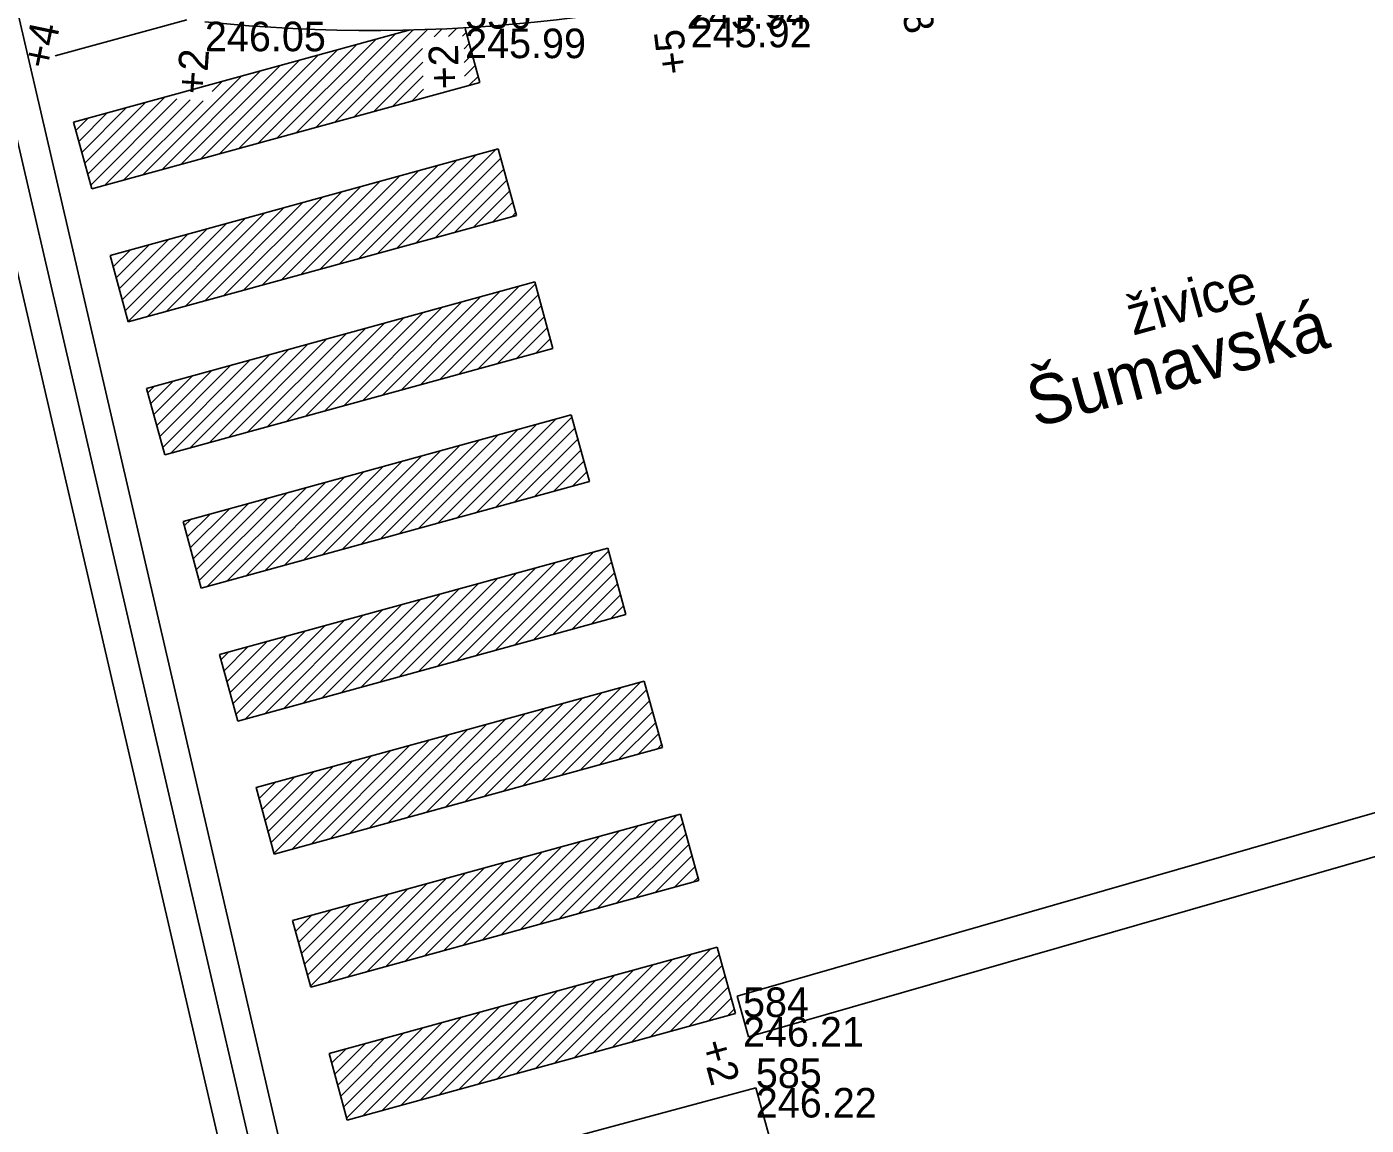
# Model space of a CAD drawing. Extents: x -599432 to -598680, y -1159407 to -1158632.
# Drawn here: x -599215.84 to -599202.25, y -1158959.67 to -1158948.52 of the extents above; entities that cross this region are included whole.
import ezdxf

# ---------------------------------------------------------------- set-up
doc = ezdxf.new("R2010")
doc.units = 0
for name, color, linetype in [('0004 VY - Body podrobné', 7, 'Continuous'), ('0005 VY - Body podrobné - čísla', 7, 'Continuous'), ('0006 VY - Body podrobné - výšky', 7, 'Continuous'), ('0024 ZA - Podezdívka', 7, 'Continuous'), ('0027 ZA - Silnice_cesta zpevněná', 7, 'Continuous'), ('0032 TE - Popis povrchu', 7, 'Continuous'), ('0048 TE - Názvy ulic _ náměstí', 7, 'Continuous'), ('0063 ZA - Doprava - vodorovné značení', 7, 'Continuous'), ('0073 TE - Výška obrubníků a zdí', 7, 'Continuous'), ('0652 PV - BKOM - kabely bez rozlišení', 7, 'Continuous'), ('0653 PV - BKOM - chranička', 7, 'Continuous')]:
    doc.layers.add(name, color=color, linetype=linetype)

msp = doc.modelspace()

# ---------------------------------------------------------------- linework, layer by layer
at = {"layer": '0004 VY - Body podrobné'}
for p, q in [((-599211.39, -1158948.54), (-599211.39, -1158948.54)), ((-599208.57, -1158958.57), (-599208.57, -1158958.57)), ((-599208.44, -1158959.29), (-599208.44, -1158959.29))]:
    msp.add_line(p, q, dxfattribs=at)
at = {"layer": '0024 ZA - Podezdívka'}
for p, q in [((-599208.629, -1158958.358), (-599184.09, -1158951.303)), ((-599208.514, -1158958.772), (-599183.95, -1158951.71)), ((-599208.514, -1158958.772), (-599208.629, -1158958.358))]:
    msp.add_line(p, q, dxfattribs=at)
at = {"layer": '0027 ZA - Silnice_cesta zpevněná'}
for p, q in [((-599214.067, -1158960.799), (-599208.44, -1158959.29)), ((-599208.44, -1158959.29), (-599207.51, -1158962.63))]:
    msp.add_line(p, q, dxfattribs=at)
msp.add_arc((-599212.336, -1158932.38), 16.179, 263.9914, 289.2961, dxfattribs=at)
at = {"layer": '0063 ZA - Doprava - vodorovné značení'}
for p, q in [((-599214.213, -1158948.45), (-599215.549, -1158948.816)), ((-599211.948, -1158948.554), (-599215.364, -1158949.491)), ((-599212.906, -1158949.543), (-599211.916, -1158948.553)), ((-599212.711, -1158949.49), (-599211.771, -1158948.549)), ((-599211.704, -1158948.623), (-599211.622, -1158948.542)), ((-599211.559, -1158948.62), (-599211.474, -1158948.535)), ((-599211.39, -1158948.54), (-599211.24, -1158949.086)), ((-599213.296, -1158949.65), (-599212.295, -1158948.65)), ((-599213.101, -1158949.596), (-599212.101, -1158948.596)), ((-599211.415, -1158948.617), (-599211.379, -1158948.581)), ((-599211.401, -1158948.745), (-599211.348, -1158948.692)), ((-599213.881, -1158949.81), (-599212.88, -1158948.81)), ((-599213.686, -1158949.757), (-599212.685, -1158948.757)), ((-599213.491, -1158949.703), (-599212.49, -1158948.703)), ((-599212.516, -1158949.436), (-599211.821, -1158948.741)), ((-599211.398, -1158948.883), (-599211.318, -1158948.803)), ((-599214.465, -1158949.971), (-599213.465, -1158948.97)), ((-599214.27, -1158949.917), (-599213.27, -1158948.917)), ((-599214.076, -1158949.864), (-599213.075, -1158948.863)), ((-599212.321, -1158949.383), (-599211.818, -1158948.879)), ((-599211.395, -1158949.022), (-599211.287, -1158948.914)), ((-599211.24, -1158949.086), (-599215.178, -1158950.167)), ((-599214.66, -1158950.024), (-599213.66, -1158949.024)), ((-599213.956, -1158949.179), (-599213.855, -1158949.077)), ((-599212.126, -1158949.329), (-599211.815, -1158949.018)), ((-599211.347, -1158949.115), (-599211.257, -1158949.025)), ((-599215.219, -1158950.018), (-599214.439, -1158949.238)), ((-599211.932, -1158949.276), (-599211.812, -1158949.156)), ((-599211.737, -1158949.222), (-599211.734, -1158949.219)), ((-599215.28, -1158949.796), (-599214.829, -1158949.345)), ((-599215.25, -1158949.907), (-599214.634, -1158949.291)), ((-599215.189, -1158950.129), (-599214.314, -1158949.253)), ((-599215.05, -1158950.131), (-599214.181, -1158949.262)), ((-599214.855, -1158950.078), (-599214.049, -1158949.272)), ((-599215.364, -1158949.491), (-599215.178, -1158950.167)), ((-599215.341, -1158949.574), (-599215.219, -1158949.452)), ((-599215.31, -1158949.685), (-599215.024, -1158949.398)), ((-599211.055, -1158949.761), (-599214.993, -1158950.842)), ((-599212.083, -1158950.769), (-599211.083, -1158949.769)), ((-599211.055, -1158949.761), (-599210.87, -1158950.436)), ((-599212.473, -1158950.876), (-599211.473, -1158949.876)), ((-599212.278, -1158950.822), (-599211.278, -1158949.822)), ((-599211.888, -1158950.715), (-599211.029, -1158949.856)), ((-599213.058, -1158951.036), (-599212.057, -1158950.036)), ((-599212.863, -1158950.983), (-599211.862, -1158949.982)), ((-599212.668, -1158950.929), (-599211.668, -1158949.929)), ((-599211.693, -1158950.662), (-599210.998, -1158949.967)), ((-599213.643, -1158951.197), (-599212.642, -1158950.196)), ((-599213.448, -1158951.143), (-599212.447, -1158950.143)), ((-599213.253, -1158951.09), (-599212.252, -1158950.089)), ((-599211.499, -1158950.608), (-599210.968, -1158950.078)), ((-599211.304, -1158950.555), (-599210.938, -1158950.189)), ((-599214.032, -1158951.304), (-599213.032, -1158950.303)), ((-599213.837, -1158951.25), (-599212.837, -1158950.25)), ((-599211.109, -1158950.502), (-599210.907, -1158950.3)), ((-599210.87, -1158950.436), (-599214.808, -1158951.517)), ((-599214.617, -1158951.464), (-599213.617, -1158950.464)), ((-599214.422, -1158951.411), (-599213.422, -1158950.41)), ((-599214.227, -1158951.357), (-599213.227, -1158950.357)), ((-599210.914, -1158950.448), (-599210.877, -1158950.411)), ((-599214.839, -1158951.403), (-599214.006, -1158950.571)), ((-599214.808, -1158951.514), (-599213.812, -1158950.517)), ((-599214.93, -1158951.07), (-599214.591, -1158950.731)), ((-599214.9, -1158951.181), (-599214.396, -1158950.678)), ((-599214.869, -1158951.292), (-599214.201, -1158950.624)), ((-599214.993, -1158950.842), (-599214.808, -1158951.517)), ((-599214.991, -1158950.848), (-599214.981, -1158950.838)), ((-599214.961, -1158950.959), (-599214.786, -1158950.785)), ((-599210.684, -1158951.111), (-599214.623, -1158952.192)), ((-599211.648, -1158952.101), (-599210.679, -1158951.132)), ((-599210.684, -1158951.111), (-599210.499, -1158951.786)), ((-599212.233, -1158952.262), (-599211.232, -1158951.261)), ((-599212.038, -1158952.208), (-599211.037, -1158951.208)), ((-599211.843, -1158952.155), (-599210.842, -1158951.154)), ((-599211.453, -1158952.048), (-599210.648, -1158951.243)), ((-599212.622, -1158952.369), (-599211.622, -1158951.368)), ((-599212.428, -1158952.315), (-599211.427, -1158951.315)), ((-599211.258, -1158951.994), (-599210.618, -1158951.354)), ((-599213.207, -1158952.529), (-599212.207, -1158951.529)), ((-599213.012, -1158952.476), (-599212.012, -1158951.475)), ((-599212.817, -1158952.422), (-599211.817, -1158951.422)), ((-599211.063, -1158951.941), (-599210.587, -1158951.465)), ((-599213.792, -1158952.69), (-599212.792, -1158951.689)), ((-599213.597, -1158952.636), (-599212.597, -1158951.636)), ((-599213.402, -1158952.583), (-599212.402, -1158951.582)), ((-599210.868, -1158951.887), (-599210.557, -1158951.576)), ((-599210.673, -1158951.834), (-599210.526, -1158951.687)), ((-599210.499, -1158951.786), (-599214.437, -1158952.867)), ((-599214.182, -1158952.797), (-599213.181, -1158951.796)), ((-599213.987, -1158952.743), (-599212.986, -1158951.743)), ((-599214.489, -1158952.679), (-599213.766, -1158951.957)), ((-599214.458, -1158952.79), (-599213.571, -1158951.903)), ((-599214.377, -1158952.85), (-599213.376, -1158951.85)), ((-599214.55, -1158952.457), (-599214.156, -1158952.064)), ((-599214.519, -1158952.568), (-599213.961, -1158952.01)), ((-599214.623, -1158952.192), (-599214.437, -1158952.867)), ((-599214.611, -1158952.235), (-599214.546, -1158952.171)), ((-599214.58, -1158952.346), (-599214.351, -1158952.117)), ((-599210.314, -1158952.461), (-599214.252, -1158953.542)), ((-599211.469, -1158953.504), (-599210.469, -1158952.503)), ((-599211.274, -1158953.45), (-599210.308, -1158952.484)), ((-599210.314, -1158952.461), (-599210.129, -1158953.136)), ((-599211.859, -1158953.611), (-599210.858, -1158952.61)), ((-599211.664, -1158953.557), (-599210.664, -1158952.557)), ((-599211.079, -1158953.397), (-599210.277, -1158952.595)), ((-599212.444, -1158953.771), (-599211.443, -1158952.771)), ((-599212.249, -1158953.718), (-599211.248, -1158952.717)), ((-599212.054, -1158953.664), (-599211.053, -1158952.664)), ((-599210.884, -1158953.343), (-599210.247, -1158952.706)), ((-599212.833, -1158953.878), (-599211.833, -1158952.878)), ((-599212.638, -1158953.825), (-599211.638, -1158952.824)), ((-599210.689, -1158953.29), (-599210.216, -1158952.817)), ((-599213.418, -1158954.039), (-599212.418, -1158953.038)), ((-599213.223, -1158953.985), (-599212.223, -1158952.985)), ((-599213.028, -1158953.932), (-599212.028, -1158952.931)), ((-599210.494, -1158953.236), (-599210.186, -1158952.928)), ((-599210.3, -1158953.183), (-599210.155, -1158953.039)), ((-599210.129, -1158953.136), (-599214.067, -1158954.217)), ((-599213.808, -1158954.146), (-599212.807, -1158953.145)), ((-599213.613, -1158954.092), (-599212.613, -1158953.092)), ((-599214.118, -1158954.031), (-599213.392, -1158953.306)), ((-599214.087, -1158954.142), (-599213.197, -1158953.252)), ((-599214.003, -1158954.199), (-599213.002, -1158953.199)), ((-599214.179, -1158953.809), (-599213.782, -1158953.413)), ((-599214.148, -1158953.92), (-599213.587, -1158953.359)), ((-599214.252, -1158953.542), (-599214.067, -1158954.217)), ((-599214.24, -1158953.587), (-599214.172, -1158953.52)), ((-599214.209, -1158953.698), (-599213.977, -1158953.466)), ((-599209.943, -1158953.811), (-599213.882, -1158954.892)), ((-599211.085, -1158954.85), (-599210.084, -1158953.85)), ((-599210.89, -1158954.797), (-599209.935, -1158953.842)), ((-599209.943, -1158953.811), (-599209.758, -1158954.486)), ((-599211.474, -1158954.957), (-599210.474, -1158953.957)), ((-599211.28, -1158954.904), (-599210.279, -1158953.903)), ((-599210.695, -1158954.743), (-599209.905, -1158953.953)), ((-599212.059, -1158955.118), (-599211.059, -1158954.117)), ((-599211.864, -1158955.064), (-599210.864, -1158954.064)), ((-599211.669, -1158955.011), (-599210.669, -1158954.01)), ((-599210.5, -1158954.69), (-599209.874, -1158954.064)), ((-599212.449, -1158955.225), (-599211.449, -1158954.224)), ((-599212.254, -1158955.171), (-599211.254, -1158954.171)), ((-599210.305, -1158954.636), (-599209.844, -1158954.175)), ((-599213.034, -1158955.385), (-599212.033, -1158954.385)), ((-599212.839, -1158955.332), (-599211.838, -1158954.331)), ((-599212.644, -1158955.278), (-599211.643, -1158954.278)), ((-599210.11, -1158954.583), (-599209.813, -1158954.286)), ((-599209.915, -1158954.529), (-599209.783, -1158954.397)), ((-599209.758, -1158954.486), (-599213.696, -1158955.567)), ((-599213.618, -1158955.545), (-599212.618, -1158954.545)), ((-599213.423, -1158955.492), (-599212.423, -1158954.492)), ((-599213.229, -1158955.439), (-599212.228, -1158954.438)), ((-599213.745, -1158955.389), (-599213.008, -1158954.652)), ((-599213.715, -1158955.5), (-599212.813, -1158954.599)), ((-599213.836, -1158955.056), (-599213.593, -1158954.813)), ((-599213.806, -1158955.167), (-599213.398, -1158954.759)), ((-599213.775, -1158955.278), (-599213.203, -1158954.706)), ((-599213.882, -1158954.892), (-599213.696, -1158955.567)), ((-599213.867, -1158954.945), (-599213.787, -1158954.866)), ((-599209.573, -1158955.161), (-599213.511, -1158956.242)), ((-599210.806, -1158956.226), (-599209.806, -1158955.225)), ((-599210.611, -1158956.172), (-599209.611, -1158955.172)), ((-599209.573, -1158955.161), (-599209.388, -1158955.836)), ((-599211.196, -1158956.332), (-599210.196, -1158955.332)), ((-599211.001, -1158956.279), (-599210.001, -1158955.279)), ((-599210.416, -1158956.119), (-599209.548, -1158955.251)), ((-599211.781, -1158956.493), (-599210.78, -1158955.493)), ((-599211.586, -1158956.439), (-599210.585, -1158955.439)), ((-599211.391, -1158956.386), (-599210.39, -1158955.386)), ((-599210.221, -1158956.065), (-599209.518, -1158955.362)), ((-599210.027, -1158956.012), (-599209.488, -1158955.473)), ((-599212.171, -1158956.6), (-599211.17, -1158955.6)), ((-599211.976, -1158956.546), (-599210.975, -1158955.546)), ((-599209.832, -1158955.958), (-599209.457, -1158955.584)), ((-599212.755, -1158956.76), (-599211.755, -1158955.76)), ((-599212.56, -1158956.707), (-599211.56, -1158955.706)), ((-599212.365, -1158956.653), (-599211.365, -1158955.653)), ((-599209.637, -1158955.905), (-599209.427, -1158955.695)), ((-599209.388, -1158955.836), (-599213.326, -1158956.917)), ((-599213.145, -1158956.867), (-599212.145, -1158955.867)), ((-599212.95, -1158956.814), (-599211.95, -1158955.813)), ((-599209.442, -1158955.851), (-599209.396, -1158955.806)), ((-599213.389, -1158956.687), (-599212.729, -1158956.027)), ((-599213.358, -1158956.798), (-599212.534, -1158955.974)), ((-599213.328, -1158956.909), (-599212.34, -1158955.92)), ((-599213.45, -1158956.465), (-599213.119, -1158956.134)), ((-599213.419, -1158956.576), (-599212.924, -1158956.081)), ((-599213.511, -1158956.243), (-599213.509, -1158956.241)), ((-599213.511, -1158956.242), (-599213.326, -1158956.917)), ((-599213.48, -1158956.354), (-599213.314, -1158956.188)), ((-599209.203, -1158956.511), (-599213.141, -1158957.592)), ((-599210.439, -1158957.576), (-599209.438, -1158956.576)), ((-599210.244, -1158957.523), (-599209.243, -1158956.523)), ((-599209.203, -1158956.511), (-599209.017, -1158957.186)), ((-599210.829, -1158957.683), (-599209.828, -1158956.683)), ((-599210.634, -1158957.63), (-599209.633, -1158956.63)), ((-599210.049, -1158957.469), (-599209.178, -1158956.599)), ((-599209.854, -1158957.416), (-599209.148, -1158956.71)), ((-599211.413, -1158957.844), (-599210.413, -1158956.843)), ((-599211.218, -1158957.79), (-599210.218, -1158956.79)), ((-599211.023, -1158957.737), (-599210.023, -1158956.736)), ((-599209.659, -1158957.362), (-599209.118, -1158956.821)), ((-599211.803, -1158957.951), (-599210.803, -1158956.95)), ((-599211.608, -1158957.897), (-599210.608, -1158956.897)), ((-599209.464, -1158957.309), (-599209.087, -1158956.932)), ((-599212.388, -1158958.111), (-599211.387, -1158957.111)), ((-599212.193, -1158958.058), (-599211.192, -1158957.057)), ((-599211.998, -1158958.004), (-599210.998, -1158957.004)), ((-599209.269, -1158957.256), (-599209.057, -1158957.043)), ((-599209.017, -1158957.186), (-599212.955, -1158958.267)), ((-599212.778, -1158958.218), (-599211.777, -1158957.218)), ((-599212.583, -1158958.165), (-599211.582, -1158957.164)), ((-599209.074, -1158957.202), (-599209.026, -1158957.154)), ((-599213.019, -1158958.035), (-599212.362, -1158957.378)), ((-599212.988, -1158958.146), (-599212.167, -1158957.325)), ((-599212.958, -1158958.257), (-599211.972, -1158957.271)), ((-599213.08, -1158957.813), (-599212.752, -1158957.485)), ((-599213.049, -1158957.924), (-599212.557, -1158957.432)), ((-599213.141, -1158957.592), (-599212.955, -1158958.267)), ((-599213.11, -1158957.702), (-599212.947, -1158957.539)), ((-599208.832, -1158957.861), (-599212.77, -1158958.942)), ((-599210.092, -1158958.933), (-599209.092, -1158957.933)), ((-599209.897, -1158958.88), (-599208.897, -1158957.879)), ((-599209.703, -1158958.826), (-599208.812, -1158957.935)), ((-599208.832, -1158957.861), (-599208.647, -1158958.536)), ((-599210.482, -1158959.04), (-599209.482, -1158958.04)), ((-599210.287, -1158958.987), (-599209.287, -1158957.986)), ((-599209.508, -1158958.773), (-599208.781, -1158958.046)), ((-599211.067, -1158959.201), (-599210.067, -1158958.2)), ((-599210.872, -1158959.147), (-599209.872, -1158958.147)), ((-599210.677, -1158959.094), (-599209.677, -1158958.093)), ((-599209.313, -1158958.719), (-599208.751, -1158958.157)), ((-599211.457, -1158959.308), (-599210.456, -1158958.307)), ((-599211.262, -1158959.254), (-599210.261, -1158958.254)), ((-599209.118, -1158958.666), (-599208.72, -1158958.268)), ((-599212.041, -1158959.468), (-599211.041, -1158958.468)), ((-599211.847, -1158959.415), (-599210.846, -1158958.414)), ((-599211.652, -1158959.361), (-599210.651, -1158958.361)), ((-599208.923, -1158958.612), (-599208.69, -1158958.379)), ((-599208.647, -1158958.536), (-599212.585, -1158959.617)), ((-599212.431, -1158959.575), (-599211.431, -1158958.575)), ((-599212.236, -1158959.522), (-599211.236, -1158958.521)), ((-599208.728, -1158958.559), (-599208.659, -1158958.49)), ((-599212.652, -1158959.372), (-599212.016, -1158958.735)), ((-599212.622, -1158959.483), (-599211.821, -1158958.682)), ((-599212.591, -1158959.594), (-599211.626, -1158958.628)), ((-599212.713, -1158959.15), (-599212.405, -1158958.842)), ((-599212.683, -1158959.261), (-599212.211, -1158958.789)), ((-599212.77, -1158958.942), (-599212.585, -1158959.617)), ((-599212.744, -1158959.039), (-599212.6, -1158958.896))]:
    msp.add_line(p, q, dxfattribs=at)
at = {"layer": '0652 PV - BKOM - kabely bez rozlišení'}
for points in [[(-599230.59, -1158974.37), (-599220.8, -1158971.75), (-599221.6, -1158968.7), (-599221.47, -1158967), (-599221.32, -1158965.59), (-599219.76, -1158963.71), (-599218.51, -1158962.9), (-599214.91, -1158961.78), (-599213.68, -1158961.96), (-599212.86, -1158962.94), (-599216.66, -1158946.55), (-599217.48, -1158945.68), (-599223.02, -1158942.57)], [(-599234.98, -1158975.02), (-599233.92, -1158975.36), (-599230.92, -1158974.46), (-599230.59, -1158974.37), (-599220.8, -1158971.75), (-599221.6, -1158968.7), (-599221.47, -1158967), (-599221.32, -1158965.59), (-599219.76, -1158963.71), (-599218.51, -1158962.9), (-599214.91, -1158961.78), (-599213.68, -1158961.96), (-599212.86, -1158962.94), (-599216.66, -1158946.55), (-599215.68, -1158946.71), (-599213.41, -1158947.28), (-599210.22, -1158947.13), (-599194.67, -1158942.89)]]:
    msp.add_lwpolyline(points, dxfattribs=at)
at = {"layer": '0653 PV - BKOM - chranička'}
for p, q in [((-599216.368, -1158946.482), (-599212.568, -1158962.872)), ((-599216.952, -1158946.618), (-599213.152, -1158963.008))]:
    msp.add_line(p, q, dxfattribs=at)

# ---------------------------------------------------------------- texts
at = {"layer": '0005 VY - Body podrobné - čísla'}
for s, p in [('556', (-599211.39, -1158948.54)), ('584', (-599208.57, -1158958.57)), ('585', (-599208.44, -1158959.29))]:
    msp.add_text(s, height=0.3, dxfattribs=at).set_placement(p)
at = {"layer": '0006 VY - Body podrobné - výšky'}
for s, p in [('245.94', (-599209.14, -1158948.54)), ('245.92', (-599209.1, -1158948.73)), ('246.05', (-599214.03, -1158948.77)), ('245.99', (-599211.39, -1158948.84)), ('246.21', (-599208.57, -1158958.87)), ('246.22', (-599208.44, -1158959.59))]:
    msp.add_text(s, height=0.3, dxfattribs=at).set_placement(p)
at = {"layer": '0032 TE - Popis povrchu'}
msp.add_text('živice', height=0.4, rotation=15.5236, dxfattribs=at).set_placement((-599204.614, -1158951.657))
at = {"layer": '0048 TE - Názvy ulic _ náměstí'}
msp.add_text('Šumavská', height=0.5, rotation=15.2857, dxfattribs=at).set_placement((-599205.603, -1158952.591))
at = {"layer": '0073 TE - Výška obrubníků a zdí'}
for s, rotation, p in [('+8', 284.3306, (-599207.018, -1158948.169)), ('+4', 78.2831, (-599215.594, -1158948.963)), ('+5', 97.0311, (-599209.123, -1158948.987)), ('+2', 86.0664, (-599214.019, -1158949.214)), ('+2', 91.2154, (-599211.452, -1158949.153)), ('+2', 285.5595, (-599209.009, -1158958.843))]:
    msp.add_text(s, height=0.3, rotation=rotation, dxfattribs=at).set_placement(p)

doc.saveas('drawing.dxf')
